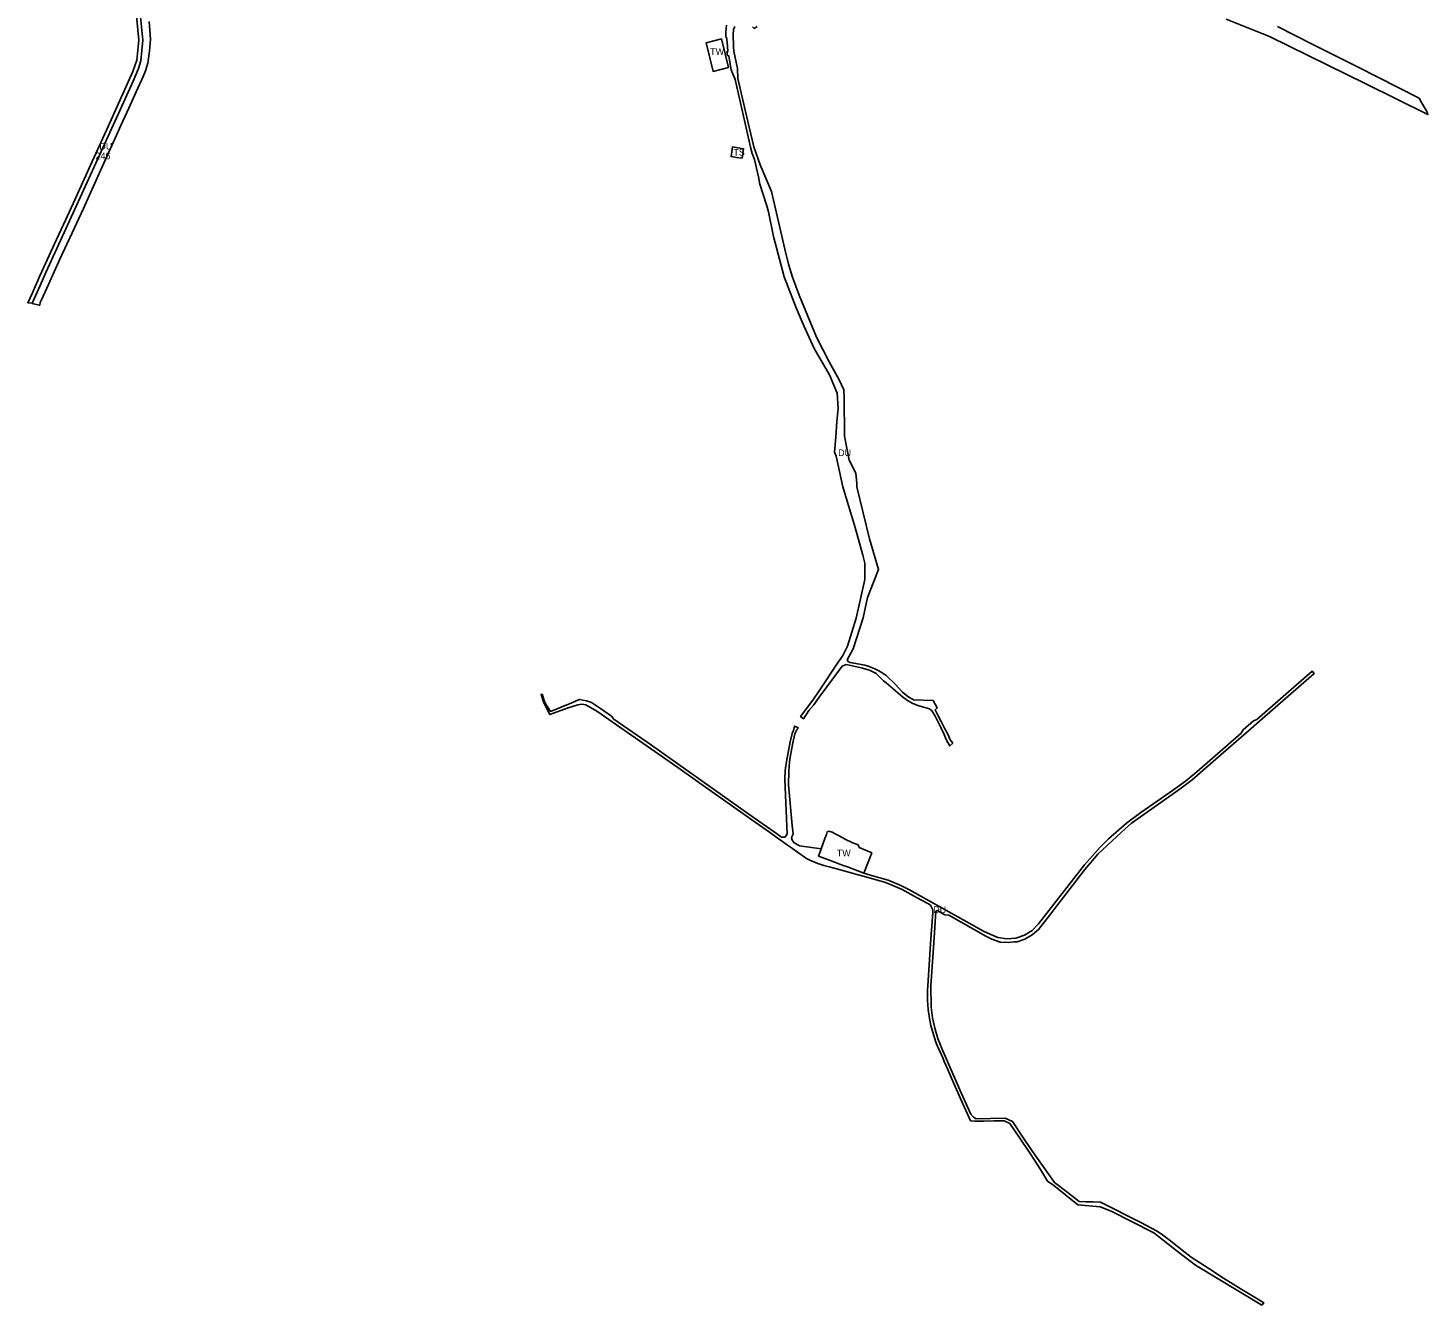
# Model space of a CAD drawing. Extents: x -521047 to -518054, y -1194945 to -1189555.
# Drawn here: x -520140 to -518054, y -1194945 to -1193041 of the extents above; entities that cross this region are included whole.
import ezdxf

# ---------------------------------------------------------------- set-up
doc = ezdxf.new("R2010")
doc.units = 0
for name, color, linetype in [('90310013', 7, 'Continuous'), ('90310023', 7, 'Continuous'), ('90320013', 7, 'Continuous'), ('90390013', 7, 'Continuous'), ('90410013', 7, 'Continuous'), ('ID_navrh', 7, 'Continuous')]:
    doc.layers.add(name, color=color, linetype=linetype)

msp = doc.modelspace()

# ---------------------------------------------------------------- linework, layer by layer
at = {"layer": '90310013'}
for points in [[(-519099.54, -1193037.16), (-519100.42, -1193046.7), (-519100.47, -1193055.02), (-519099.79, -1193055.02), (-519098.49, -1193062.14), (-519098.14, -1193068.98), (-519097.38, -1193076.11), (-519099.18, -1193076.82), (-519098.12, -1193082.46), (-519096.34, -1193082.48), (-519094.99, -1193089.06), (-519092.79, -1193103.81), (-519086.83, -1193117.76), (-519069.34, -1193194.44), (-519063.8, -1193218.73), (-519061.2, -1193228.34), (-519057.96, -1193237.27), (-519051.78, -1193263.19), (-519049.8, -1193274.26), (-519040.03, -1193304.65), (-519037.03, -1193315.32), (-519029.64, -1193352.06), (-519013.6, -1193412.23), (-518995.72, -1193458.59), (-518983.73, -1193485.98), (-518969.16, -1193519.14), (-518945.93, -1193558.15), (-518934.47, -1193585.52), (-518933.01, -1193608.51), (-518935.29, -1193627.86), (-518936.87, -1193650.95), (-518938.89, -1193673.47), (-518936.17, -1193679.58), (-518926.27, -1193725.26), (-518907.68, -1193785.6), (-518896.5, -1193826.92), (-518893.29, -1193838.77), (-518893.26, -1193863.08), (-518906.17, -1193921.14), (-518919.27, -1193962.65), (-518926.25, -1193976.62), (-518929.34, -1193981.24), (-518933.03, -1193986.3), (-518961.6, -1194029.39), (-518970.85, -1194043.01), (-518989.19, -1194067.6), (-518984.64, -1194070.77), (-518976.81, -1194058.82), (-518969.27, -1194050.28), (-518961.57, -1194038.67), (-518927.19, -1193992.35), (-518921.36, -1193990.1), (-518901.17, -1193994.65), (-518897.11, -1193995.69), (-518891.75, -1193996.93), (-518886.53, -1193998.68), (-518881.5, -1194000.92), (-518876.72, -1194003.63), (-518865.76, -1194014.41), (-518861.8, -1194017.37), (-518840.81, -1194035.16), (-518837.43, -1194038.35), (-518829.92, -1194043.82), (-518821.77, -1194048.27), (-518813.11, -1194051.65), (-518804.1, -1194053.89), (-518797.05, -1194056.07), (-518793.56, -1194058.95), (-518788.94, -1194065.87), (-518784.2, -1194075.75), (-518779.68, -1194085.15), (-518775.15, -1194094.55), (-518773.38, -1194099.24), (-518770.34, -1194105.7), (-518770.01, -1194106.27), (-518767.02, -1194111.44), (-518762.33, -1194107.13)], [(-518762.33, -1194107.13), (-518766.41, -1194102.26), (-518767.38, -1194099.7), (-518768.35, -1194097.16), (-518768.35, -1194097.15), (-518769.47, -1194094.94), (-518774.55, -1194084.96), (-518779.64, -1194074.99), (-518784.06, -1194066.31), (-518788.48, -1194057.64), (-518785.58, -1194054.84), (-518788.68, -1194049.26), (-518791.79, -1194043.69), (-518820.8, -1194042.81), (-518829.44, -1194037.71), (-518837.23, -1194031.38), (-518847.72, -1194019.68), (-518862.25, -1194005.95), (-518864.46, -1194004.33), (-518868.96, -1194001.44), (-518873.62, -1193998.81), (-518878.43, -1193996.47), (-518883.37, -1193994.4), (-518888.41, -1193992.64), (-518893.56, -1193991.17), (-518896.17, -1193990.58), (-518915.51, -1193987.1), (-518917.8, -1193986.11), (-518919.42, -1193984.21), (-518919.72, -1193983.02), (-518910.79, -1193966.72), (-518895.73, -1193920.57), (-518889.3, -1193889.95), (-518872.98, -1193848.37), (-518886.46, -1193802.5), (-518905.57, -1193725.38), (-518905.61, -1193720.26), (-518906.72, -1193704.58), (-518916.83, -1193685.28), (-518923.59, -1193649.53), (-518924.44, -1193591.77), (-518924.55, -1193580.35), (-518931.74, -1193565.63), (-518946.48, -1193538.74), (-518965.5, -1193501.95), (-518991.48, -1193439.69), (-519001.34, -1193412.48), (-519007.46, -1193393.47), (-519012.64, -1193370.77), (-519032.72, -1193285.1), (-519049.46, -1193245.15), (-519058.78, -1193218.39), (-519067.63, -1193180.4), (-519082.57, -1193116.69), (-519083.39, -1193101.82), (-519088.85, -1193075.94), (-519089.42, -1193069.44), (-519089.5, -1193051.02), (-519089.11, -1193043.23), (-519087.08, -1193038.9)], [(-519060.88, -1193039.35), (-519058.32, -1193041.95), (-519054.02, -1193039.03)], [(-518992.34, -1194084.24), (-518998.31, -1194081.79), (-518999.95, -1194088.17), (-519001.62, -1194092.79), (-519004.84, -1194105.44), (-519010.43, -1194134.4), (-519012.2, -1194148.13), (-519012.79, -1194161.44), (-519009.11, -1194242.54), (-519012.22, -1194247.18), (-519017.78, -1194247.27), (-519025.2, -1194242.02), (-519066.22, -1194213.01), (-519211.54, -1194110.23), (-519267.59, -1194071.65), (-519271.05, -1194066.85), (-519282.43, -1194059.02), (-519287.59, -1194055.46), (-519300.97, -1194046.69), (-519308.16, -1194044.03), (-519319.06, -1194042.03), (-519330.1, -1194047.22), (-519362.08, -1194059.92), (-519370.51, -1194046.68), (-519374.32, -1194034.25), (-519375.87, -1194034.77), (-519371.75, -1194047.1), (-519364.98, -1194060.74), (-519364.84, -1194061.02), (-519363.03, -1194064.67), (-519335.55, -1194054.45), (-519321.14, -1194050.16), (-519315.34, -1194049.18), (-519309.32, -1194050.2), (-519292.85, -1194059.74), (-519172.35, -1194143.44), (-519146.5, -1194161.75), (-519139.27, -1194166.84), (-519117.67, -1194182.15), (-519078.64, -1194209.72), (-519061.74, -1194221.72), (-519035.71, -1194240.08), (-519023.94, -1194248.41), (-519017.53, -1194252.96), (-519008.87, -1194259.09), (-519001.41, -1194264.41), (-518993.95, -1194269.72), (-518980.26, -1194279.31), (-518975.52, -1194281.45), (-518966.08, -1194285.71), (-518962.17, -1194287.03), (-518954.36, -1194289.64), (-518946.44, -1194291.75), (-518937.1, -1194294.31), (-518910.54, -1194301.58), (-518905.25, -1194303.03), (-518892.05, -1194306.64), (-518872.91, -1194311.92), (-518865.77, -1194314.1), (-518862.69, -1194315.05), (-518851.56, -1194319.21), (-518838.06, -1194325.4), (-518816.36, -1194337.16), (-518799.64, -1194346.49), (-518795.83, -1194348.62), (-518791.99, -1194355.76), (-518792.24, -1194359.26), (-518793.68, -1194380.64), (-518794.42, -1194391.59), (-518794.97, -1194399.7), (-518795.42, -1194406.33), (-518799.63, -1194468.85), (-518800.14, -1194475.82), (-518800.02, -1194490.26), (-518799.05, -1194504.36), (-518797.21, -1194517.5), (-518794.95, -1194528.17), (-518788.05, -1194551.39), (-518785.78, -1194557.7), (-518782.8, -1194564.37), (-518779.91, -1194571.02), (-518777.47, -1194576.55), (-518775.18, -1194581.75), (-518770.31, -1194592.82), (-518764.33, -1194606.4), (-518760.69, -1194614.68), (-518754.77, -1194628.15), (-518749.32, -1194640.47), (-518736.23, -1194670.16), (-518729.2, -1194670.98), (-518716.54, -1194670.67), (-518701.17, -1194670.37), (-518685.8, -1194670.06), (-518677.5, -1194674.21), (-518662.7, -1194695.92), (-518647.9, -1194717.64), (-518639.9, -1194730.32), (-518631.9, -1194743.01), (-518621.23, -1194759.93), (-518611.71, -1194766.87), (-518575.86, -1194795.7), (-518542.69, -1194798.26), (-518526.37, -1194804.79), (-518463.01, -1194837.27), (-518428.24, -1194864.28), (-518400.82, -1194885.57), (-518302.06, -1194944.78), (-518299.16, -1194941.37), (-518311.68, -1194933.74), (-518331.86, -1194921.42), (-518344.66, -1194913.71), (-518359.22, -1194904.68), (-518380.99, -1194890.59), (-518407.42, -1194873.57), (-518416.02, -1194866.37), (-518440.03, -1194847.7), (-518449.87, -1194840.31), (-518458.12, -1194834.75), (-518481.99, -1194821.99), (-518542.37, -1194791.36), (-518553.06, -1194791.06), (-518563.47, -1194790.77), (-518573.88, -1194790.47), (-518592.32, -1194776.2), (-518610.75, -1194761.93), (-518627.58, -1194738.16), (-518644.41, -1194714.39), (-518658.98, -1194692.9), (-518673.54, -1194671.4), (-518679.04, -1194668.76), (-518684.53, -1194666.12), (-518706.04, -1194666.63), (-518727.55, -1194667.14), (-518731.66, -1194664.89), (-518735.68, -1194660.28), (-518749.75, -1194628.33), (-518778.85, -1194562.27), (-518784.67, -1194547.47), (-518789.28, -1194532.25), (-518792.66, -1194516.7), (-518794.77, -1194500.94), (-518795.17, -1194469.16), (-518789.82, -1194390.1), (-518787.62, -1194357.85), (-518785.49, -1194356.68), (-518774.24, -1194362.95), (-518768.4, -1194363.91), (-518713.15, -1194395.12), (-518704.16, -1194399.65), (-518691.62, -1194403.86), (-518679.67, -1194404.43), (-518670.64, -1194403.6), (-518666.66, -1194403.24), (-518655.26, -1194399.4), (-518644.16, -1194393.22), (-518634.54, -1194384.93), (-518613.59, -1194357.67), (-518605.97, -1194347.8), (-518565.48, -1194295.54), (-518546.38, -1194272.96), (-518525.09, -1194252.86), (-518505.53, -1194235), (-518496.1, -1194226.49), (-518427.2, -1194178.07), (-518421.43, -1194173.75), (-518405.98, -1194161.92), (-518389.76, -1194148.03), (-518359.17, -1194121.38), (-518317.92, -1194085.37), (-518305.19, -1194074.33), (-518223.96, -1194003.53), (-518226.78, -1194000.03), (-518309.55, -1194072.16), (-518314.52, -1194073.94), (-518329.88, -1194087.32), (-518332.7, -1194092.34), (-518398.75, -1194149.91), (-518415.71, -1194163.89), (-518433.41, -1194176.9), (-518482.17, -1194210.72), (-518503.56, -1194226.5), (-518530.28, -1194249.78), (-518542.85, -1194262.27), (-518566.27, -1194288.86), (-518634.76, -1194376.7), (-518644.23, -1194386.38), (-518655.68, -1194393.54), (-518668.49, -1194397.81), (-518681.94, -1194398.95), (-518695.28, -1194396.89), (-518705.84, -1194392.3), (-518716.88, -1194387.49), (-518827.82, -1194325.64), (-518840.84, -1194318.92), (-518858.91, -1194311.54), (-518883.44, -1194304.45), (-518885.16, -1194303.95), (-518895.2, -1194301.05), (-518919.44, -1194291.86), (-518925.72, -1194289.49), (-518930.57, -1194287.65), (-518941.17, -1194283.6), (-518946.35, -1194281.61), (-518962.42, -1194275.59), (-518959.58, -1194267.74), (-518958.46, -1194264.63), (-518990.61, -1194260.15), (-518992.56, -1194259.17), (-518998.9, -1194255.97), (-519001.67, -1194251.84), (-519002.57, -1194248.44), (-519000.5, -1194242.27), (-519001.58, -1194230.24), (-519007.1, -1194169.38), (-519006.82, -1194148.88), (-519005.71, -1194135.09), (-519004.5, -1194128.01), (-519000.87, -1194106.75), (-518997.57, -1194093.58), (-518994.52, -1194086.35), (-518992.34, -1194084.24)]]:
    msp.add_lwpolyline(points, dxfattribs=at)
at = {"layer": '90310023'}
msp.add_lwpolyline([(-519979.35, -1193018.09), (-519975.45, -1193059.33), (-519978.09, -1193089.18), (-519984.32, -1193106.32), (-520021.04, -1193188.07), (-520047.22, -1193245.62), (-520070.77, -1193297.42), (-520084.24, -1193326.9), (-520097.84, -1193356.45), (-520122.68, -1193410.82), (-520133.9, -1193436.21), (-520140.41, -1193450.83), (-520134.88, -1193451.49), (-520134.2, -1193451.67), (-520133.56, -1193450.26), (-520122.34, -1193424.94), (-520113.77, -1193405.48), (-520097.51, -1193370.06), (-520083.91, -1193340.59), (-520070.47, -1193311.24), (-520008.16, -1193174.24), (-519983.64, -1193120.33), (-519975.56, -1193101.44), (-519972.17, -1193090.33), (-519969.42, -1193059.31), (-519973.19, -1193019.52)], dxfattribs=at)
at = {"layer": '90320013'}
for points in [[(-519973.19, -1193019.52), (-519969.42, -1193059.31), (-519972.17, -1193090.33), (-519975.56, -1193101.44), (-519983.64, -1193120.33), (-520008.16, -1193174.24), (-520070.47, -1193311.24), (-520083.91, -1193340.59), (-520097.51, -1193370.06), (-520113.77, -1193405.48), (-520122.34, -1193424.94), (-520133.56, -1193450.26), (-520134.2, -1193451.67), (-520123.6, -1193454.5), (-520122.83, -1193454.58), (-520122.19, -1193450.64), (-520120.13, -1193446.45), (-520110.08, -1193423.75), (-520093.16, -1193385.99), (-520074.37, -1193346.48), (-520057.96, -1193310.06), (-520032.44, -1193253.64), (-520010.57, -1193205.51), (-520002.08, -1193186.73), (-519990.26, -1193160.72), (-519979.15, -1193136.45), (-519968.9, -1193113.5), (-519965.3, -1193105.27), (-519962.06, -1193093.75), (-519959.22, -1193075.94), (-519957.98, -1193057.97), (-519959.95, -1193031.63)], [(-518355.07, -1193028.15), (-518290.52, -1193053.74), (-518147.01, -1193124.62), (-518054.34, -1193170.39), (-518055.5, -1193166.62), (-518056.58, -1193164.78), (-518064.02, -1193152.08), (-518067.56, -1193146.04), (-518128.95, -1193114.67), (-518158.26, -1193099.67), (-518179.48, -1193089.1), (-518225.89, -1193065.68), (-518278.49, -1193039.24)]]:
    msp.add_lwpolyline(points, dxfattribs=at)
at = {"layer": '90390013'}
for points in [[(-519096.56, -1193100.18), (-519107.08, -1193057.58), (-519130.14, -1193063.54), (-519119.61, -1193106.06), (-519096.56, -1193100.18)], [(-518895.2, -1194301.05), (-518883.22, -1194270.86), (-518884.06, -1194270.49), (-518901.77, -1194262.69), (-518903.43, -1194258.95), (-518912.68, -1194255.11), (-518916.45, -1194253.54), (-518918.24, -1194252.79), (-518922.65, -1194250.42), (-518931.93, -1194245.39), (-518937.68, -1194242.28), (-518942.14, -1194239.95), (-518947.28, -1194238.51), (-518949.41, -1194239.58), (-518950.81, -1194243.44), (-518953.02, -1194249.57), (-518958.46, -1194264.63), (-518959.58, -1194267.74), (-518962.42, -1194275.59), (-518946.35, -1194281.61), (-518941.17, -1194283.6), (-518930.57, -1194287.65), (-518925.72, -1194289.49), (-518919.44, -1194291.86), (-518895.2, -1194301.05)]]:
    msp.add_lwpolyline(points, dxfattribs=at)
at = {"layer": '90410013'}
msp.add_lwpolyline([(-519076.43, -1193235.38), (-519075.3, -1193228.25), (-519074.18, -1193221.13), (-519082.52, -1193219.82), (-519090.87, -1193218.52), (-519091.82, -1193225.66), (-519092.77, -1193232.8), (-519084.6, -1193234.09), (-519076.43, -1193235.38)], dxfattribs=at)

# ---------------------------------------------------------------- texts
at = {"layer": '90310013'}
msp.add_text('DU', height=10, dxfattribs=at).set_placement((-518933.3, -1193679.36))
msp.add_text('DU', height=10, rotation=0, dxfattribs=at).set_placement((-518791.59, -1194360.49))
at = {"layer": '90310023'}
msp.add_text('DU', height=10, rotation=0, dxfattribs=at).set_placement((-520034.11, -1193222.52))
at = {"layer": '90390013'}
for p in [(-519124.01, -1193081.37), (-518935.3, -1194275.95)]:
    msp.add_text('TW', height=10, rotation=360, dxfattribs=at).set_placement(p)
at = {"layer": '90410013'}
msp.add_text('TS', height=10, rotation=0, dxfattribs=at).set_placement((-519089.41, -1193231.58))
at = {"layer": 'ID_navrh'}
msp.add_text('246', height=10, rotation=360, dxfattribs=at).set_placement((-520039.91, -1193236.91))

doc.saveas('drawing.dxf')
